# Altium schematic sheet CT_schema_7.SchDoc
size 226 x 144 mm
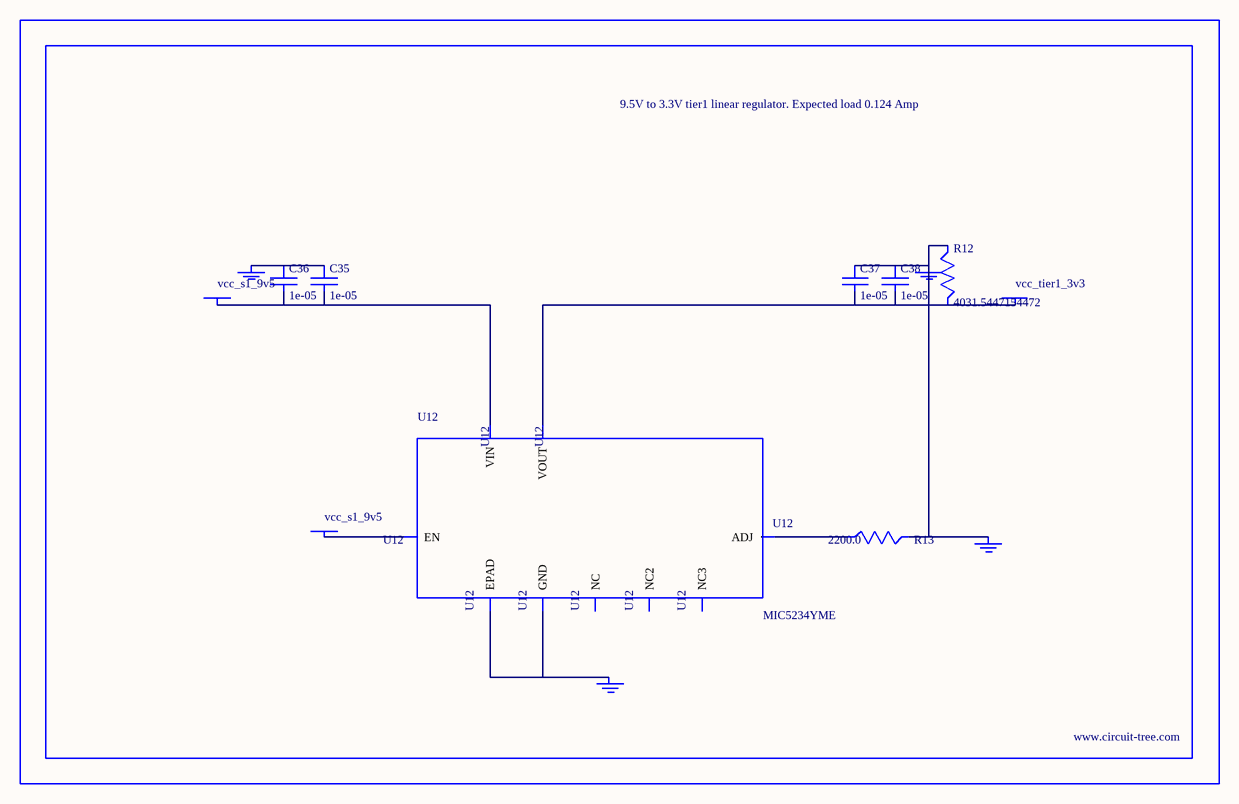
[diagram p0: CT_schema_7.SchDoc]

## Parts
BORDER6  (no value)
C35  1e-05  [C1210]
C36  1e-05  [C1210]
C37  1e-05  [C1210]
C38  1e-05  [C1210]
GND_INSTANCE_6_0  (no value)
GND_INSTANCE_6_1  (no value)
GND_INSTANCE_6_2  (no value)
GND_INSTANCE_6_3  (no value)
POWER_INSTANCE_6_0  vcc_tier1_3v3
POWER_INSTANCE_6_1  vcc_s1_9v5
POWER_INSTANCE_6_2  vcc_s1_9v5
R12  4031.5447154472  [R0603]
R13  2200.0  [R0603]
U12  MIC5234YME  [SOIC-8_EP]

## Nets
NetC35_1: C35.1 C36.1 GND_INSTANCE_6_3.0(GND)
NetC35_2: C35.2 C36.2 POWER_INSTANCE_6_2.0(PWR) U12.8(VIN)
NetC37_1: C37.1 C38.1 GND_INSTANCE_6_0.0(GND) GND_INSTANCE_6_1.0(GND) R12.1 R13.2
NetC37_2: C37.2 C38.2 POWER_INSTANCE_6_0.0(PWR) R12.2 U12.1(VOUT)
NetGND_INSTANCE_6_2_0: GND_INSTANCE_6_2.0(GND) U12.7(GND) U12.EPAD
NetPOWER_INSTANCE_6_1_0: POWER_INSTANCE_6_1.0(PWR) U12.5(EN)
NetR13_1: R13.1 U12.4(ADJ)

Not connected (* = marked no-connect by the designer): U12 2(NC) 3(NC2) 6(NC3)

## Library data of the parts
BORDER6 = BORDER_PAGE6
C35-C38 = C1210C106K5PACTU
GND_INSTANCE_6_0-GND_INSTANCE_6_3 = GND
POWER_INSTANCE_6_0-POWER_INSTANCE_6_2 = PWR
R12 = R12
R13 = RC0603JR-072K2L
